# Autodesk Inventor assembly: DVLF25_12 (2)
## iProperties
Created: 2010-03
Part Number: DVLF25_12 (2)
Document SubType Name: Assembly
Designer: TB
Mass: 193.296 g
Surface Area: 621.198 cm^2
Volume: 193.296 cm^3
Density: 1 g/cm^3
Description: KM DVLF 25/12 - 100 mm
Slaglengde: 100.000 mm
Author: TB
